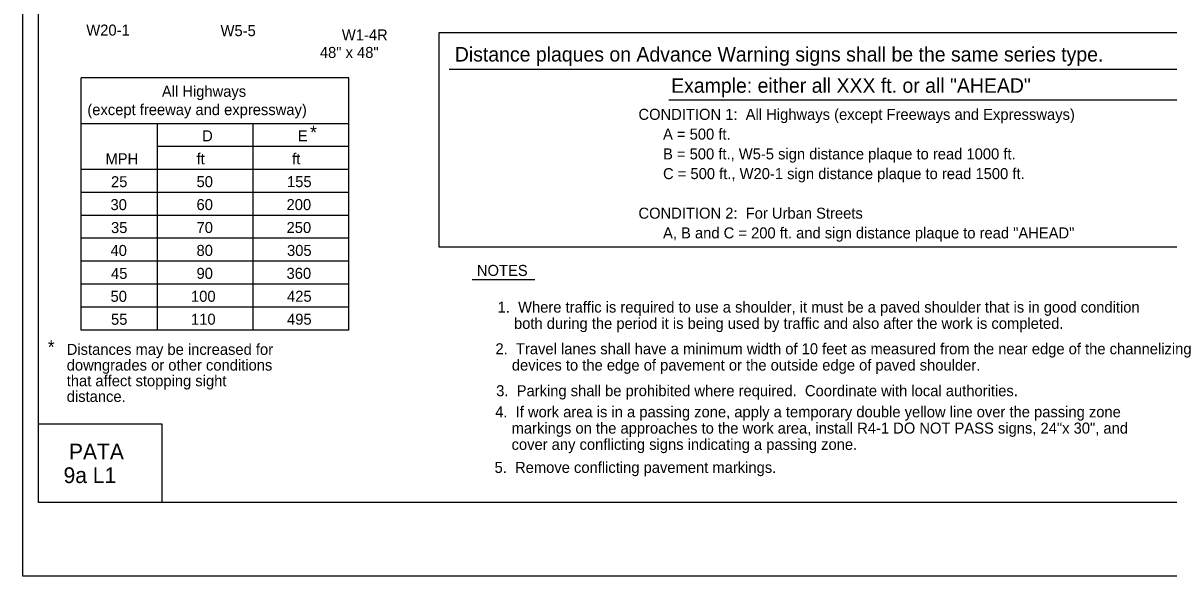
# Model space of a CAD drawing. Extents: x -14145 to -13521, y 30244 to 30661.
# Drawn here: x -13756.17 to -13734.34, y 30532.81 to 30543.35 of the extents above; entities that cross this region are included whole.
import ezdxf

# ---------------------------------------------------------------- set-up
doc = ezdxf.new("R2010")
doc.units = 0
for name, color, linetype in [('1', 7, 'Continuous'), ('10', 7, 'Continuous'), ('2', 7, 'Continuous'), ('3', 7, 'Continuous'), ('4', 7, 'Continuous'), ('61', 7, 'Continuous')]:
    doc.layers.add(name, color=color, linetype=linetype)

msp = doc.modelspace()

# ---------------------------------------------------------------- linework, layer by layer
at = {"layer": '1'}
for p, q in [((-13755.062, 30537.497), (-13755.062, 30542.305)), ((-13749.962, 30542.305), (-13755.062, 30542.305)), ((-13749.962, 30537.497), (-13749.962, 30542.305)), ((-13749.962, 30541.431), (-13755.063, 30541.431)), ((-13753.605, 30537.497), (-13753.605, 30541.431)), ((-13751.783, 30537.497), (-13751.783, 30541.431)), ((-13749.962, 30540.994), (-13753.605, 30540.994)), ((-13749.962, 30540.557), (-13755.063, 30540.557)), ((-13749.962, 30540.12), (-13755.063, 30540.12)), ((-13749.962, 30539.683), (-13755.063, 30539.683)), ((-13749.962, 30539.246), (-13755.063, 30539.246)), ((-13749.962, 30538.809), (-13755.063, 30538.809)), ((-13749.962, 30538.372), (-13755.063, 30538.372)), ((-13749.962, 30537.935), (-13755.063, 30537.935)), ((-13749.962, 30537.497), (-13755.062, 30537.497))]:
    msp.add_line(p, q, dxfattribs=at)
at = {"layer": '10'}
for p, q in [((-13755.874, 30534.207), (-13755.874, 30556.777)), ((-13755.874, 30535.707), (-13753.524, 30535.707)), ((-13753.524, 30535.707), (-13753.524, 30534.207)), ((-13724.422, 30534.207), (-13755.874, 30534.207))]:
    msp.add_line(p, q, dxfattribs=at)
at = {"layer": '2'}
for p, q in [((-13748.047, 30542.473), (-13728.096, 30542.473)), ((-13743.86, 30541.888), (-13732.423, 30541.888)), ((-13746.418, 30538.457), (-13747.609, 30538.457))]:
    msp.add_line(p, q, dxfattribs=at)
msp.add_lwpolyline([(-13748.239, 30543.172), (-13727.821, 30543.172), (-13727.821, 30539.079), (-13748.239, 30539.079)], close=True, dxfattribs=at)
at = {"layer": '61'}
msp.add_lwpolyline([(-13756.174, 30558.307), (-13723.174, 30558.307), (-13723.174, 30532.807), (-13756.174, 30532.807)], close=True, dxfattribs=at)

# ---------------------------------------------------------------- texts
at = {"layer": '1'}
for s, p in [('CONDITION 1:  All Highways (except Freeways and Expressways)', (-13744.44, 30541.504)), ('      A = 500 ft.', (-13744.44, 30541.127)), ('      B = 500 ft., W5-5 sign distance plaque to read 1000 ft.', (-13744.44, 30540.75)), ('      C = 500 ft., W20-1 sign distance plaque to read 1500 ft.', (-13744.44, 30540.374)), ('CONDITION 2:  For Urban Streets', (-13744.44, 30539.62)), ('      A, B and C = 200 ft. and sign distance plaque to read "AHEAD"', (-13744.44, 30539.244))]:
    msp.add_text(s, height=0.21, dxfattribs=at).set_placement(p)
at = {"layer": '2'}
for s, height, p in [('W20-1', 0.21, (-13754.965, 30543.11)), ('W5-5', 0.21, (-13752.406, 30543.099)), ('W1-4R', 0.21, (-13750.094, 30543.018)), ('48" x 48"', 0.21, (-13750.513, 30542.684)), ('Distance plaques on Advance Warning signs shall be the same series type.', 0.2772, (-13747.941, 30542.616)), ('Example: either all XXX ft. or all "AHEAD"', 0.2772, (-13743.817, 30542.02)), ('*', 0.252, (-13750.7, 30541.14)), ('D', 0.21, (-13752.756, 30541.094)), ('E', 0.21, (-13750.932, 30541.094)), ('MPH', 0.21, (-13754.599, 30540.657)), ('ft', 0.21, (-13752.863, 30540.657)), ('ft', 0.21, (-13751.041, 30540.657)), ('25', 0.21, (-13754.494, 30540.22)), ('50', 0.21, (-13752.864, 30540.221)), ('155', 0.21, (-13751.139, 30540.221)), ('30', 0.21, (-13754.504, 30539.783)), ('60', 0.21, (-13752.864, 30539.784)), ('200', 0.21, (-13751.148, 30539.784)), ('35', 0.21, (-13754.494, 30539.346)), ('70', 0.21, (-13752.864, 30539.347)), ('250', 0.21, (-13751.148, 30539.347)), ('40', 0.21, (-13754.504, 30538.909)), ('80', 0.21, (-13752.864, 30538.91)), ('305', 0.21, (-13751.139, 30538.91)), ('NOTES', 0.21, (-13747.52, 30538.529)), ('45', 0.21, (-13754.494, 30538.472)), ('90', 0.21, (-13752.864, 30538.473)), ('360', 0.21, (-13751.148, 30538.473)), ('50', 0.21, (-13754.503, 30538.035)), ('100', 0.21, (-13752.969, 30538.036)), ('425', 0.21, (-13751.139, 30538.036)), ('1.  Where traffic is required to use a shoulder, it must be a paved shoulder that is in good condition', 0.21, (-13747.125, 30537.83)), ('55', 0.21, (-13754.494, 30537.597)), ('110', 0.21, (-13752.969, 30537.599)), ('495', 0.21, (-13751.139, 30537.599)), ('    both during the period it is being used by traffic and also after the work is completed.', 0.21, (-13747.125, 30537.52)), ('*', 0.252, (-13755.699, 30537.048)), ('Distances may be increased for ', 0.21, (-13755.338, 30537.024)), ('2.  Travel lanes shall have a minimum width of 10 feet as measured from the near edge of the channelizing', 0.21, (-13747.166, 30537.035)), ('downgrades or other conditions ', 0.21, (-13755.338, 30536.725)), ('    devices to the edge of pavement or the outside edge of paved shoulder.', 0.21, (-13747.166, 30536.725)), ('that affect stopping sight ', 0.21, (-13755.338, 30536.426)), ('distance.', 0.21, (-13755.338, 30536.127)), ('3.  Parking shall be prohibited where required.  Coordinate with local authorities.', 0.21, (-13747.152, 30536.236)), ('4.  If work area is in a passing zone, apply a temporary double yellow line over the passing zone', 0.21, (-13747.171, 30535.833)), ('    markings on the approaches to the work area, install R4-1 DO NOT PASS signs, 24"x 30", and', 0.21, (-13747.171, 30535.523)), ('    cover any conflicting signs indicating a passing zone.', 0.21, (-13747.171, 30535.213)), ('5.  Remove conflicting pavement markings.', 0.21, (-13747.183, 30534.774))]:
    msp.add_text(s, height=height, dxfattribs=at).set_placement(p)
at = {"layer": '3'}
msp.add_text('All Highways', height=0.20979, rotation=360, dxfattribs=at).set_placement((-13753.525, 30541.943))
msp.add_text('(except freeway and expressway)', height=0.21, dxfattribs=at).set_placement((-13754.945, 30541.594))
at = {"layer": '4'}
for s, p in [('PATA', (-13755.296, 30535.03)), ('9a L1', (-13755.399, 30534.58))]:
    msp.add_text(s, height=0.3, dxfattribs=at).set_placement(p)

doc.saveas('drawing.dxf')
